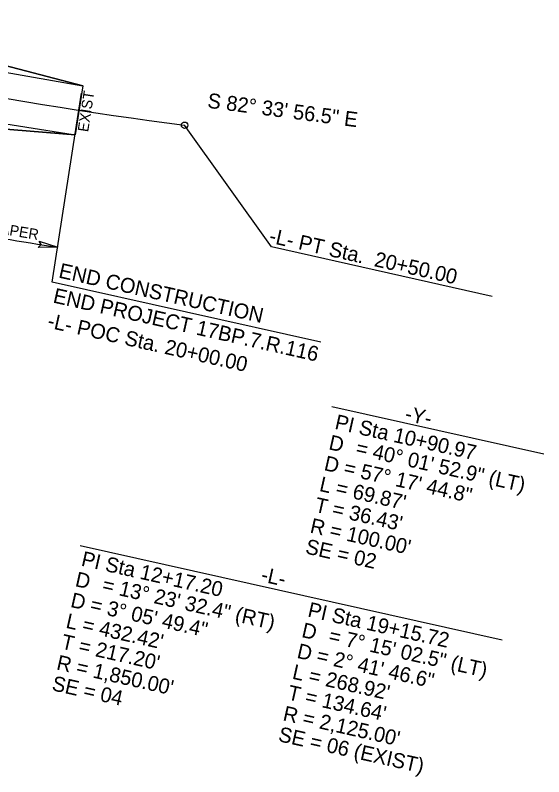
# Model space of a CAD drawing. Extents: x 1784740 to 1786163, y 841056 to 841833.
# Drawn here: x 1785915.1 to 1786162.6, y 841055.6 to 841412.6 of the extents above; entities that cross this region are included whole.
import ezdxf

# ---------------------------------------------------------------- set-up
doc = ezdxf.new("R2010")
doc.units = 0
for name, color, linetype in [('Prop Dimension', 7, 'Continuous'), ('Prop EOT', 7, 'Continuous'), ('Prop Horizontal Alignment', 7, 'Continuous'), ('Prop Horizontal Alignment Curve and Spiral Data', 7, 'Continuous'), ('Prop Horizontal Alignment Direction Label', 7, 'Continuous'), ('Prop Horizontal Alignment Station Label', 7, 'Continuous'), ('Prop Horizontal Alignment Tick Large', 7, 'Continuous'), ('Prop Paved Shoulder', 7, 'Continuous'), ('Prop Shade Light', 7, 'Continuous'), ('Prop Terminator CELL', 7, 'Continuous')]:
    doc.layers.add(name, color=color, linetype=linetype)

msp = doc.modelspace()

# ---------------------------------------------------------------- linework, layer by layer
at = {"layer": 'Prop Dimension'}
msp.add_arc((1786269.36, 843468.14), 2190, 259.86941, 261.21755, dxfattribs=at)
at = {"layer": 'Prop EOT'}
for p, q in [((1785897.7, 841388.08), (1785946.67, 841379.44)), ((1785946.67, 841379.44), (1785943.13, 841356.55)), ((1785893.48, 841364.46), (1785943.13, 841356.55))]:
    msp.add_line(p, q, dxfattribs=at)
at = {"layer": 'Prop Horizontal Alignment'}
msp.add_arc((1786269.36, 843468.14), 2125, 255.31501, 262.56569, dxfattribs=at)
at = {"layer": 'Prop Horizontal Alignment Curve and Spiral Data'}
for p, q in [((1786063.33, 841229.23), (1786162.61, 841206.97)), ((1785945.57, 841164.08), (1786143.06, 841119.79))]:
    msp.add_line(p, q, dxfattribs=at)
at = {"layer": 'Prop Horizontal Alignment Station Label'}
for p, q in [((1785932.45, 841287.44), (1785944.91, 841368.06)), ((1786035.13, 841303.95), (1785994.41, 841361)), ((1786138.41, 841280.79), (1786035.13, 841303.95)), ((1786058.14, 841259.25), (1785932.45, 841287.44))]:
    msp.add_line(p, q, dxfattribs=at)
msp.add_circle((1785994.41, 841361), 1.5, dxfattribs=at)
at = {"layer": 'Prop Horizontal Alignment Tick Large'}
for q in [(1785946.13, 841375.96), (1785943.69, 841360.15)]:
    msp.add_line((1785944.91, 841368.06), q, dxfattribs=at)
at = {"layer": 'Prop Paved Shoulder'}
for p, q in [((1785898.4, 841392.02), (1785946.67, 841379.44)), ((1785892.78, 841360.52), (1785943.13, 841356.55))]:
    msp.add_line(p, q, dxfattribs=at)
at = {"layer": 'Prop Shade Light'}
for p, q in [((1785946.67, 841379.44), (1785898.4, 841392.02)), ((1785897.7, 841388.08), (1785946.67, 841379.44)), ((1785893.48, 841364.46), (1785943.13, 841356.55)), ((1785943.13, 841356.55), (1785892.78, 841360.52))]:
    msp.add_line(p, q, dxfattribs=at)
at = {"layer": 'Prop Terminator CELL'}
msp.add_lwpolyline([(1785926.33, 841306.72), (1785934.98, 841303.82), (1785925.8, 841303.62), (1785927.18, 841305.03)], close=True, dxfattribs=at)

# ---------------------------------------------------------------- texts
at = {"layer": 'Prop Dimension'}
for s, rotation, p in [('EXIST', 81.2176, (1785949.22, 841357.59)), ("50' TAPER", 350.482, (1785893.26, 841312.62))]:
    msp.add_text(s, height=5, rotation=rotation, dxfattribs=at).set_placement(p)
at = {"layer": 'Prop Horizontal Alignment Curve and Spiral Data'}
for s, p in [('-Y-', (1786097.19, 841222.68)), ('PI Sta 10+90.97', (1786064.38, 841218.75)), ('D', (1786061.53, 841209.14)), ('= 40%%d 01\' 52.9" (LT)', (1786074.14, 841206.61)), ('D = 57%%d 17\' 44.8"', (1786059.34, 841199.38)), ("L = 69.87'", (1786057.16, 841189.62)), ("T = 36.43'", (1786054.97, 841179.87)), ("R = 100.00'", (1786052.78, 841170.11)), ('SE = 02', (1786050.59, 841160.35)), ('PI Sta 12+17.20', (1785945.63, 841154.61)), ('-L-', (1786029.79, 841147.25)), ('D', (1785942.78, 841145)), ('= 13%%d 23\' 32.4" (RT)', (1785955.39, 841142.48)), ('D = 3%%d 05\' 49.4"', (1785940.59, 841135.24)), ('PI Sta 19+15.72', (1786051.68, 841130.76)), ("L = 432.42'", (1785938.41, 841125.49)), ('D', (1786048.84, 841121.15)), ("T = 217.20'", (1785936.22, 841115.73)), ('= 7%%d 15\' 02.5" (LT)', (1786061.44, 841118.62)), ('D = 2%%d 41\' 46.6"', (1786046.65, 841111.39)), ("R = 1,850.00'", (1785934.03, 841105.97)), ("L = 268.92'", (1786044.46, 841101.63)), ('SE = 04', (1785931.84, 841096.21)), ("T = 134.64'", (1786042.27, 841091.87)), ("R = 2,125.00'", (1786040.08, 841082.12)), ('SE = 06 (EXIST)', (1786037.89, 841072.36))]:
    msp.add_text(s, height=7, rotation=347.3599, dxfattribs=at).set_placement(p)
at = {"layer": 'Prop Horizontal Alignment Direction Label'}
msp.add_text('S 82%%d 33\' 56.5" E', height=7, rotation=352.5657, dxfattribs=at).set_placement((1786004.81, 841369.22))
at = {"layer": 'Prop Horizontal Alignment Station Label'}
for s, p in [('-L- PT Sta.  20+50.00', (1786033.59, 841306.03)), ('END CONSTRUCTION', (1785935.04, 841289.65)), ('END PROJECT 17BP.7.R.116', (1785932.42, 841277.94)), ('-L- POC Sta. 20+00.00', (1785929.79, 841266.23))]:
    msp.add_text(s, height=7, rotation=347.3599, dxfattribs=at).set_placement(p)

doc.saveas('drawing.dxf')
